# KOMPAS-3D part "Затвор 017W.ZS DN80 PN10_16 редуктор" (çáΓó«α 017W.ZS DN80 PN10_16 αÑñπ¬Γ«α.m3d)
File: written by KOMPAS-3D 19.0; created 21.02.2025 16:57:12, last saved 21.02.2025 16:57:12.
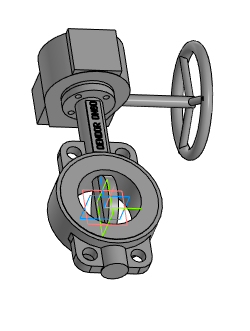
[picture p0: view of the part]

Document properties: Автор: Евгений; Полное имя файла: Затвор 017W.ZS DN80 PN10_16 редуктор.a3d

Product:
- Part/product: Затвор 017W.ZS DN80 PN10_16 редуктор
    Масса: 11.0822

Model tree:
1. Операция без истории:1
